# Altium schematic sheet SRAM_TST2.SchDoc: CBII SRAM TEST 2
size A3; Engineer: SHOWELL; DocumentNumber: 1; Revision: 1.00; SheetNumber: 1; SheetTotal: 1
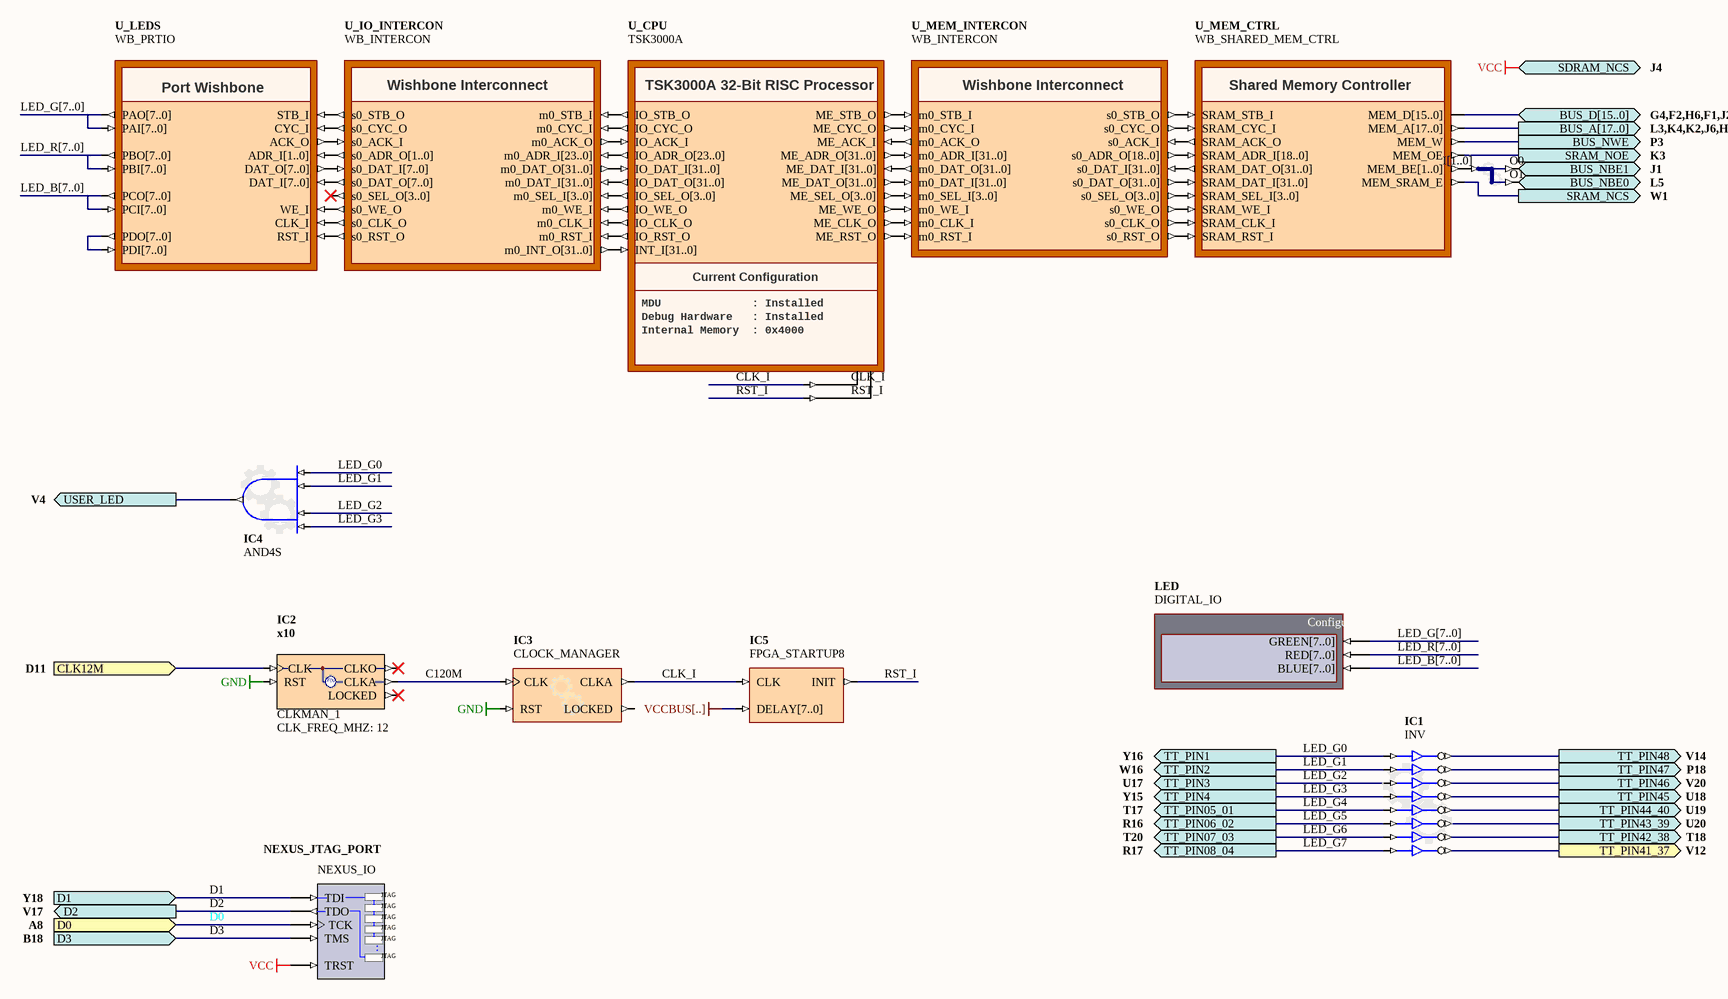
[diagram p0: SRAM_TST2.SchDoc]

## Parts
IC1  INV
IC2  CLKMAN_1  CLK_FREQ_MHZ: 12  ClkA_Operation: x10
IC3  CLOCK_MANAGER
IC4  AND4S
IC5  FPGA_STARTUP8
LED  DIGITAL_IO
NEXUS_JTAG_PORT  NEXUS_IO
U3000  BUS_JS  (value not drawn)
U_CPU  TSK3000A
U_IO_INTERCON  WB_INTERCON
U_LEDS  WB_PRTIO
U_MEM_CTRL  WB_SHARED_MEM_CTRL
U_MEM_INTERCON  WB_INTERCON

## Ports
BUS_A[17..0] (out, see L3,K4,K2,J6,H4,E3,D2,G5,M1,M2,M3,N1,N2,U4,W3,V6,U7,W6), BUS_D[15..0] (bidir, see G4,F2,H6,F1,J2,G3,H3,H2,L1,V2,V1,U3,U1,T3,T2,T1), BUS_NBE0 (out, see L5), BUS_NBE1 (out, see J1), BUS_NWE (out, see P3), CLK12M (in, see D11), D0 (in, see A8), D1 (in, see Y18), D2 (out, see V17), D3 (in, see B18), SDRAM_NCS (out, see J4), SRAM_NCS (out, see W1), SRAM_NOE (out, see K3), TT_PIN1 (out, see Y16), TT_PIN2 (out, see W16), TT_PIN3 (out, see U17), TT_PIN4 (out, see Y15), TT_PIN05_01 (out, see T17), TT_PIN06_02 (out, see R16), TT_PIN07_03 (out, see T20), TT_PIN08_04 (out, see R17), TT_PIN41_37 (out, see V12), TT_PIN42_38 (out, see T18), TT_PIN43_39 (out, see U20), TT_PIN44_40 (out, see U19), TT_PIN45 (out, see U18), TT_PIN46 (out, see V20), TT_PIN47 (out, see P18), TT_PIN48 (out, see V14), USER_LED (out, see V4)

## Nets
GND: IC2.RST IC3.RST
VCC: NEXUS_JTAG_PORT.TRST ; port SDRAM_NCS
BUS_NBE0: U3000.O1 ; port BUS_NBE0
BUS_NBE1: U3000.O0 ; port BUS_NBE1
BUS_NWE: U_MEM_CTRL.MEM_W ; port BUS_NWE
C120M: IC2.CLKA IC3.CLK
CLK12M: IC2.CLK ; port CLK12M
CLK_I: IC3.CLKA IC5.CLK U_CPU.CLK_I
D0: NEXUS_JTAG_PORT.TCK ; port D0
D1: NEXUS_JTAG_PORT.TDI ; port D1
D2: NEXUS_JTAG_PORT.TDO ; port D2
D3: NEXUS_JTAG_PORT.TMS ; port D3
LED_G0: IC1.I0 IC4.I3 ; port TT_PIN1
LED_G1: IC1.I1 IC4.I2 ; port TT_PIN2
LED_G2: IC1.I2 IC4.I1 ; port TT_PIN3
LED_G3: IC1.I3 IC4.I0 ; port TT_PIN4
LED_G4: IC1.I4 ; port TT_PIN05_01
LED_G5: IC1.I5 ; port TT_PIN06_02
LED_G6: IC1.I6 ; port TT_PIN07_03
LED_G7: IC1.I7 ; port TT_PIN08_04
RST_I: IC5.INIT U_CPU.RST_I
SRAM_NCS: U_MEM_CTRL.MEM_SRAM_E ; port SRAM_NCS
SRAM_NOE: U_MEM_CTRL.MEM_OE ; port SRAM_NOE
TT_PIN41_37: IC1.O7 ; port TT_PIN41_37
TT_PIN42_38: IC1.O6 ; port TT_PIN42_38
TT_PIN43_39: IC1.O5 ; port TT_PIN43_39
TT_PIN44_40: IC1.O4 ; port TT_PIN44_40
TT_PIN45: IC1.O3 ; port TT_PIN45
TT_PIN46: IC1.O2 ; port TT_PIN46
TT_PIN47: IC1.O1 ; port TT_PIN47
TT_PIN48: IC1.O0 ; port TT_PIN48
USER_LED: IC4.O ; port USER_LED
NetU3000_I[1..0]: U3000.I[1..0] U_MEM_CTRL.MEM_BE[1..0]
NetU_CPU_INT_I[31..0]: U_CPU.INT_I[31..0] U_IO_INTERCON.m0_INT_O[31..0]
NetU_CPU_IO_ACK_I: U_CPU.IO_ACK_I U_IO_INTERCON.m0_ACK_O
NetU_CPU_IO_ADR_O[23..0]: U_CPU.IO_ADR_O[23..0] U_IO_INTERCON.m0_ADR_I[23..0]
NetU_CPU_IO_CLK_O: U_CPU.IO_CLK_O U_IO_INTERCON.m0_CLK_I
NetU_CPU_IO_CYC_O: U_CPU.IO_CYC_O U_IO_INTERCON.m0_CYC_I
NetU_CPU_IO_DAT_I[31..0]: U_CPU.IO_DAT_I[31..0] U_IO_INTERCON.m0_DAT_O[31..0]
NetU_CPU_IO_DAT_O[31..0]: U_CPU.IO_DAT_O[31..0] U_IO_INTERCON.m0_DAT_I[31..0]
NetU_CPU_IO_RST_O: U_CPU.IO_RST_O U_IO_INTERCON.m0_RST_I
NetU_CPU_IO_SEL_O[3..0]: U_CPU.IO_SEL_O[3..0] U_IO_INTERCON.m0_SEL_I[3..0]
NetU_CPU_IO_STB_O: U_CPU.IO_STB_O U_IO_INTERCON.m0_STB_I
NetU_CPU_IO_WE_O: U_CPU.IO_WE_O U_IO_INTERCON.m0_WE_I
NetU_CPU_ME_ACK_I: U_CPU.ME_ACK_I U_MEM_INTERCON.m0_ACK_O
NetU_CPU_ME_ADR_O[31..0]: U_CPU.ME_ADR_O[31..0] U_MEM_INTERCON.m0_ADR_I[31..0]
NetU_CPU_ME_CLK_O: U_CPU.ME_CLK_O U_MEM_INTERCON.m0_CLK_I
NetU_CPU_ME_CYC_O: U_CPU.ME_CYC_O U_MEM_INTERCON.m0_CYC_I
NetU_CPU_ME_DAT_I[31..0]: U_CPU.ME_DAT_I[31..0] U_MEM_INTERCON.m0_DAT_O[31..0]
NetU_CPU_ME_DAT_O[31..0]: U_CPU.ME_DAT_O[31..0] U_MEM_INTERCON.m0_DAT_I[31..0]
NetU_CPU_ME_RST_O: U_CPU.ME_RST_O U_MEM_INTERCON.m0_RST_I
NetU_CPU_ME_SEL_O[3..0]: U_CPU.ME_SEL_O[3..0] U_MEM_INTERCON.m0_SEL_I[3..0]
NetU_CPU_ME_STB_O: U_CPU.ME_STB_O U_MEM_INTERCON.m0_STB_I
NetU_CPU_ME_WE_O: U_CPU.ME_WE_O U_MEM_INTERCON.m0_WE_I
NetU_IO_INTERCON_s0_ACK_I: U_IO_INTERCON.s0_ACK_I U_LEDS.ACK_O
NetU_IO_INTERCON_s0_ADR_O[1..0]: U_IO_INTERCON.s0_ADR_O[1..0] U_LEDS.ADR_I[1..0]
NetU_IO_INTERCON_s0_CLK_O: U_IO_INTERCON.s0_CLK_O U_LEDS.CLK_I
NetU_IO_INTERCON_s0_CYC_O: U_IO_INTERCON.s0_CYC_O U_LEDS.CYC_I
NetU_IO_INTERCON_s0_DAT_I[7..0]: U_IO_INTERCON.s0_DAT_I[7..0] U_LEDS.DAT_O[7..0]
NetU_IO_INTERCON_s0_DAT_O[7..0]: U_IO_INTERCON.s0_DAT_O[7..0] U_LEDS.DAT_I[7..0]
NetU_IO_INTERCON_s0_RST_O: U_IO_INTERCON.s0_RST_O U_LEDS.RST_I
NetU_IO_INTERCON_s0_STB_O: U_IO_INTERCON.s0_STB_O U_LEDS.STB_I
NetU_IO_INTERCON_s0_WE_O: U_IO_INTERCON.s0_WE_O U_LEDS.WE_I
NetU_MEM_CTRL_SRAM_ACK_O: U_MEM_CTRL.SRAM_ACK_O U_MEM_INTERCON.s0_ACK_I
NetU_MEM_CTRL_SRAM_ADR_I[18..0]: U_MEM_CTRL.SRAM_ADR_I[18..0] U_MEM_INTERCON.s0_ADR_O[18..0]
NetU_MEM_CTRL_SRAM_CLK_I: U_MEM_CTRL.SRAM_CLK_I U_MEM_INTERCON.s0_CLK_O
NetU_MEM_CTRL_SRAM_CYC_I: U_MEM_CTRL.SRAM_CYC_I U_MEM_INTERCON.s0_CYC_O
NetU_MEM_CTRL_SRAM_DAT_I[31..0]: U_MEM_CTRL.SRAM_DAT_I[31..0] U_MEM_INTERCON.s0_DAT_O[31..0]
NetU_MEM_CTRL_SRAM_DAT_O[31..0]: U_MEM_CTRL.SRAM_DAT_O[31..0] U_MEM_INTERCON.s0_DAT_I[31..0]
NetU_MEM_CTRL_SRAM_RST_I: U_MEM_CTRL.SRAM_RST_I U_MEM_INTERCON.s0_RST_O
NetU_MEM_CTRL_SRAM_SEL_I[3..0]: U_MEM_CTRL.SRAM_SEL_I[3..0] U_MEM_INTERCON.s0_SEL_O[3..0]
NetU_MEM_CTRL_SRAM_STB_I: U_MEM_CTRL.SRAM_STB_I U_MEM_INTERCON.s0_STB_O
NetU_MEM_CTRL_SRAM_WE_I: U_MEM_CTRL.SRAM_WE_I U_MEM_INTERCON.s0_WE_O

Not connected (* = marked no-connect by the designer): IC2 CLKO* LOCKED*; IC3 LOCKED; IC5 DELAY[7..0]; LED BLUE[7..0] GREEN[7..0] RED[7..0]; U_IO_INTERCON s0_SEL_O[3..0]*; U_LEDS PAI[7..0] PAO[7..0] PBI[7..0] PBO[7..0] PCI[7..0] PCO[7..0] PDI[7..0] PDO[7..0]; U_MEM_CTRL MEM_A[17..0] MEM_D[15..0]

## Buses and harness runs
bus LED_B[7..0]
bus LED_G[7..0]
bus LED_R[7..0]

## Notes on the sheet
- Labels drawn without touching a wire or pin: VCCBUS[..]

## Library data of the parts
IC1 = INV: Configurable Inverter; ConfiguratorName: GENERIC_BUFFER; ConfigurationParameters: {}Version[1.1]{}SignalCount[8]{}SignalWidth0[1]{}OutputOption0[Inverted]{}SignalWidth1[1]{}OutputOption1[Inverted]{}SignalWidth2[1]{}OutputOption2[Inverted]{}SignalWidth3[1]{}OutputOption3[Inverted]{}SignalWidth4[1]{}OutputOption4[Inverted]{}SignalWidth5[1]{}OutputOption5[Inverted]{}SignalWidth6[1]{}OutputOption6[Inverted]{}SignalWidth7[1]{}OutputOption7[Inverted]{}EnableMode[None]{}ShowPinNames[False]{}
IC2 = CLKMAN_1: Single Operational Output Clock Manager; Clk_Count: 1
IC3 = CLOCKMANAGER: Configurable Clock Manager; ConfiguratorName: GENERIC_CLOCKMANAGER; ConfigurationParameters: {}Version[1.0]{}Option_Configuration[object _1: TClockManagerPersist / VersionMajor [ 0 / VersionMinor [ 0 / InputFreq [ 120.000000000000000000 / InputName [ 'CLK' / OutputTargets [ < / item / Name [ 'CLKA' / OutFreqMin [ 50.000000000000000000 / OutFreqMax [ 50.000000000000000000 / OutPostDivider [ 1.000000000000000000 / end> / OutputDevices [ < / item / Name [ 'Spartan3AN' / Valid [ True / OutputActuals [ < / item / Name [ 'CLK0' / Multipler [ 1.000000000000000000 / Divider [ 1.000000000000000000 / OutFreq [ 120.000000000000000000 / OutputMap [ 1 / end / item / Name [ 'CLK90' / Multipler [ 1.000000000000000000 / Divider [ 1.000000000000000000 / OutPhase [ 90.000000000000000000 / OutFreq [ 120.000000000000000000 / OutputMap [ 2 / end / item / Name [ 'CLK180' / Multipler [ 1.000000000000000000 / Divider [ 1.000000000000000000 / OutPhase [ 180.000000000000000000 / OutFreq [ 120.000000000000000000 / OutputMap [ 3 / end / item / Name [ 'CLK270' / Multipler [ 1.000000000000000000 / Divider [ 1.000000000000000000 / OutPhase [ 270.000000000000000000 / OutFreq [ 120.000000000000000000 / OutputMap [ 4 / end / item / Name [ 'CLK2X' / Multipler [ 2.000000000000000000 / Divider [ 1.000000000000000000 / OutFreq [ 240.000000000000000000 / OutputMap [ 5 / end / item / Name [ 'CLKDV' / Multipler [ 1.000000000000000000 / Divider [ 16.000000000000000000 / OutFreq [ 7.500000000000000000 / OutputMap [ 6 / end / item / Name [ 'CLK2X180' / Multipler [ 1.000000000000000000 / Divider [ 1.000000000000000000 / OutPhase [ 180.000000000000000000 / OutFreq [ 240.000000000000000000 / OutputMap [ 7 / end / item / Name [ 'CLKFX' / Multipler [ 5.000000000000000000 / Divider [ 12.000000000000000000 / OutFreq [ 50.000000000000000000 / OutputMap [ 0 / end / item / Name [ 'CLKFX180' / Multipler [ 1.000000000000000000 / Divider [ 1.000000000000000000 / OutPhase [ 180.000000000000000000 / OutFreq [ 50.000000000000000000 / OutputMap [ 8 / end> / InternalActuals [ <> / CustomVars [ <> / end> / MinInputFreq [ 1.000000000000000000 / MaxInputFreq [ 280.000000000000000000 / MinOutputFreq [ 18.000000000000000000 / MaxOutputFreq [ 210.000000000000000000 / MaxOutputCount [ 9 / end]{}
IC4 = GATE: Configurable Generic Gate; ConfiguratorName: GENERIC_GATE; ConfigurationParameters: {}Version[1.1]{}GateKind[AND]{}BusInput[False]{}GateInputType[Bit]{}GateOutputOption[Normal]{}BusWidth[8]{}RegisterOutputs[False]{}NegativeClockEdge[False]{}InputCount[4]{}InputInvert0[False]{}InputInvert1[False]{}InputInvert2[False]{}InputInvert3[False]{}
IC5 = FPGA_STARTUP8: FPGA Startup With 8 Bit Delay
LED = DIGITAL_IO: Configurable Digital IO; NEXUS_CORE: Instrument; NEXUS_JTAG_DEVICE: True; NEXUS_JTAG_ORDER: 0; ConfigurationParameters: {}Version[2.0]{}StorageType[3]{}InterfaceType[Parallel]{}SchCompWidth[140]{}Input0Name[GREEN{1}7..0{2}]{}Input0Width[8]{}Input0InitValue[0]{}Input0Kind[LEDs]{}Input0LEDStyle[Green]{}Input1Name[RED{1}7..0{2}]{}Input1Width[8]{}Input1InitValue[0]{}Input1Kind[LEDs]{}Input1LEDStyle[Red]{}Input2Name[BLUE{1}7..0{2}]{}Input2Width[8]{}Input2InitValue[0]{}Input2Kind[LEDs]{}Input2LEDStyle[Blue]{}NoOutputs[ ]{}Designator[LED]{}InternalID[0]{}
NEXUS_JTAG_PORT = NEXUS_JTAG_PORT: Soft Nexus-Chain Connector; NEXUS_JTAG_CONNECTOR: True
U3000 = BUS_JS: Configurable Bus Joiner/Splitter; ConfiguratorName: GENERIC_BUS_JS; ConfigurationParameters: {}Version[1.1]{}SplitterJoinerType[Splitter]{}SignalCount[2]{}SignalWidth0[1]{}GapBelow0[1000000]{}ConnectionType0[Pin]{}SignalWidth1[1]{}GapBelow1[1000000]{}ConnectionType1[Pin]{}ShowPinNames[True]{}
U_CPU = TSK3000A: TSK3000A OCD Microprocessor; Nexus_JTAG_Device: True; Nexus_Core: Processor_OCDS; Nexus_JTAG_Order: 0; ConfigurationParameters: {}Version[1.1]{}Option_Processor[0]{}Option_Memory[4]{}Option_ExactMemory[16k]{}Option_MDU[0]{}Option_OCDS[0]{}Option_Shifter[0]{}Option_InterruptCount[32]{}Option_DebugWhenReset[0]{}; ConfiguratorName: FPGA_MCU32; Memory_Configuration: Record[AUTOIMPORT]{}AutoImport_Peripherals[False]{}AutoImport_Memory[False]{n}Record[CODE_EXPORT]{}ExportType[1]{n}Record[NEXUS_CORE]{}ComponentDesignator[IRAM]{}Memory_Depth[8k]{}Memory_UsageType[ram]{}Memory_Configuration[]{}Memory_External[False]{}Memory_Speed[1]{}ProgramDownloadAddress[8k]{}Memory_BusType[TSK3000:addr_bus]{}Memory_Mau[8]{}Memory_MatchedComponent[]{}Memory_Description[]{}Memory_FillBitPattern[]{}Memory_IncludeDependencies[False]{}Memory_ByLoadAddress[False]{}Memory_CopyDuringInit[False]{}Memory_NoCopyDuringInit[False]{}Memory_Interrupts[]{n}Record[NEXUS_CORE]{}ComponentDesignator[IROM]{}Memory_Depth[8k]{}Memory_UsageType[rom]{}Memory_Configuration[]{}Memory_External[False]{}Memory_Speed[1]{}ProgramDownloadAddress[0]{}Memory_BusType[TSK3000:addr_bus]{}Memory_Mau[8]{}Memory_MatchedComponent[]{}Memory_Description[]{}Memory_FillBitPattern[]{}Memory_IncludeDependencies[False]{}Memory_ByLoadAddress[False]{}Memory_CopyDuringInit[False]{}Memory_NoCopyDuringInit[False]{}Memory_Interrupts[]{n}Record[NEXUS_CORE]{}ComponentDesignator[XRAM]{}Memory_Depth[512K]{}Memory_UsageType[ram]{}Memory_Configuration[]{}Memory_External[False]{}Memory_Speed[1]{}ProgramDownloadAddress[0x10000000]{}Memory_BusType[TSK3000:addr_bus]{}Memory_Mau[8]{}Memory_MatchedComponent[]{}Memory_Description[U_MEM_INTERCON]{}Memory_FillBitPattern[]{}Memory_IncludeDependencies[False]{}Memory_ByLoadAddress[False]{}Memory_CopyDuringInit[False]{}Memory_NoCopyDuringInit[False]{}Memory_Interrupts[]{n}Record[PERIPHERAL]{}ComponentDesignator[LEDS]{}Memory_Depth[0x0004]{}Memory_UsageType[peripheral]{}Memory_Configuration[]{}Memory_External[False]{}Memory_Speed[1]{}ProgramDownloadAddress[0xFF000000]{}Memory_BusType[TSK3000:addr_bus]{}Memory_Mau[8]{}Memory_MatchedComponent[]{}Memory_Description[U_IO_INTERCON]{}Memory_FillBitPattern[]{}Memory_IncludeDependencies[False]{}Memory_ByLoadAddress[False]{}Memory_CopyDuringInit[False]{}Memory_NoCopyDuringInit[False]{}Memory_Interrupts[]{n}Record[PHYSICAL_MEMORY]{}ComponentDesignator[IRAM]{}Memory_Depth[8k]{}Memory_UsageType[ram]{}Memory_Configuration[]{}Memory_External[False]{}Memory_Speed[1]{}ProgramDownloadAddress[8k]{}Memory_BusType[TSK3000:addr_bus]{}Memory_Mau[8]{}Memory_MatchedComponent[]{}Memory_Description[]{}Memory_FillBitPattern[]{}Memory_IncludeDependencies[False]{}Memory_ByLoadAddress[False]{}Memory_CopyDuringInit[False]{}Memory_NoCopyDuringInit[False]{}Memory_Interrupts[]{n}Record[PHYSICAL_MEMORY]{}ComponentDesignator[IROM]{}Memory_Depth[8k]{}Memory_UsageType[rom]{}Memory_Configuration[]{}Memory_External[False]{}Memory_Speed[1]{}ProgramDownloadAddress[0]{}Memory_BusType[TSK3000:addr_bus]{}Memory_Mau[8]{}Memory_MatchedComponent[]{}Memory_Description[]{}Memory_FillBitPattern[]{}Memory_IncludeDependencies[False]{}Memory_ByLoadAddress[False]{}Memory_CopyDuringInit[False]{}Memory_NoCopyDuringInit[False]{}Memory_Interrupts[]{n}Record[PHYSICAL_MEMORY]{}ComponentDesignator[XRAM]{}Memory_Depth[512K]{}Memory_UsageType[ram]{}Memory_Configuration[]{}Memory_External[False]{}Memory_Speed[1]{}ProgramDownloadAddress[0x10000000]{}Memory_BusType[TSK3000:addr_bus]{}Memory_Mau[8]{}Memory_MatchedComponent[]{}Memory_Description[U_MEM_INTERCON]{}Memory_FillBitPattern[]{}Memory_IncludeDependencies[False]{}Memory_ByLoadAddress[False]{}Memory_CopyDuringInit[False]{}Memory_NoCopyDuringInit[False]{}Memory_Interrupts[]{n}; ChildModel1: TSK3000A_MCU; ChildModel2: TSK3000A_MDU; ChildModel3: TSK3000A_OCDS; ChildModel4: TSK3000A_Shift_Barrel; ChildModel5: TSK3000A_Shift_Sequential; ChildModel6: Mult_32x32; ChildModel7: m33x33
U_IO_INTERCON = WB_INTERCON: Configurable Wishbone Interconnect; ConfigurationParameters: {}Version[1.0]{}UnusedInterrupts[1]{}MasterAddressBits[1]{}Name0[LEDS]{}Kind0[0]{}SpaceAfter0[4]{}Address_Base0[0]{}Address_Bits0[2]{}Address_Mode0[1]{}Address_DecodeWidth0[8]{}DataWidth0[2]{}UsedInterrupts0[ ]
U_LEDS = WB_PRTIO: Configurable Port Wishbone; ChildModel: PRTIO4X8_W; ConfigurationParameters: {}Version[1.0]{}PortCount[4]{}BusWidth[8]{}PortKind[0]{}
U_MEM_CTRL = WB_SHARED_MEM_CTRL: Configurable Shared Memory Controller; ConfigurationParameters: {}Version[2.0]{}SRAMOption_MemoryEnabled[True]{}SRAMOption_ClockScheme[0]{}SRAMOption_MemorySize[9]{}SRAMOption_MemoryLayout[1]{}SRAMOption_GuiPortLayout[0]{}SRAMOption_GuiExtraSpace[4]{}SRAMOption_AddressSetup[1]{}SRAMOption_WritePulse[1]{}SRAMOption_WriteHold[1]{}FLASHOption_MemoryEnabled[False]{}FLASHOption_ClockScheme[0]{}FLASHOption_MemorySize[0]{}FLASHOption_MemoryLayout[0]{}FLASHOption_GuiPortLayout[2]{}FLASHOption_GuiExtraSpace[4]{}FLASHOption_AddressSetup[6]{}FLASHOption_WritePulse[6]{}FLASHOption_WriteHold[6]{}SDRAMOption_MemoryEnabled[False]{}SDRAMOption_ClockScheme[0]{}SDRAMOption_MemorySize[3]{}SDRAMOption_MemoryLayout[3]{}SDRAMOption_GuiPortLayout[1]{}SDRAMOption_GuiExtraSpace[4]{}SDRAMOption_Frequency[100]{}SDRAMOption_RefreshInterval[1]{}SDRAMOption_RefreshPrescaler[145]{}SDRAMOption_BusWidth[1]{}SDRAMOption_BusMode[1]{}SDRAMOption_BusType[0]{}SDRAMOption_BurstLength[0]{}SDRAMOption_Timing_tCL[3]{}SDRAMOption_Timing_tMRD[2]{}SDRAMOption_Timing_tRCD[2]{}SDRAMOption_Timing_tRFC[2]{}SDRAMOption_Timing_tRP[2]{}SDRAMOption_Timing_tWR[2]{}SDRAMOption_KeepRowOpen[True]{}SDRAMOption_IsCached[True]{}SDRAMOption_RefreshRate[0]{}USBOption_MemoryEnabled[False]{}USBOption_ClockScheme[0]{}USBOption_MemorySize[0]{}USBOption_MemoryLayout[0]{}USBOption_GuiPortLayout[3]{}USBOption_GuiExtraSpace[4]{}USBOption_AddressSetup[2]{}USBOption_WritePulse[2]{}USBOption_WriteHold[2]{}Option_DisableUnusedPins[True]{}Option_LastView[1]{}Option_ComponentVersion[1]{}; ChildModel: WB_SDRAM_256x32
U_MEM_INTERCON = WB_INTERCON: Configurable Wishbone Interconnect; ConfigurationParameters: {}Version[1.0]{}UnusedInterrupts[2]{}MasterAddressBits[0]{}Name0[XRAM]{}Kind0[2]{}SpaceAfter0[4]{}Address_Base0[268435456]{}Address_Bits0[19]{}Address_Mode0[1]{}Address_DecodeWidth0[6]{}DataWidth0[0]{}UsedInterrupts0[ ]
